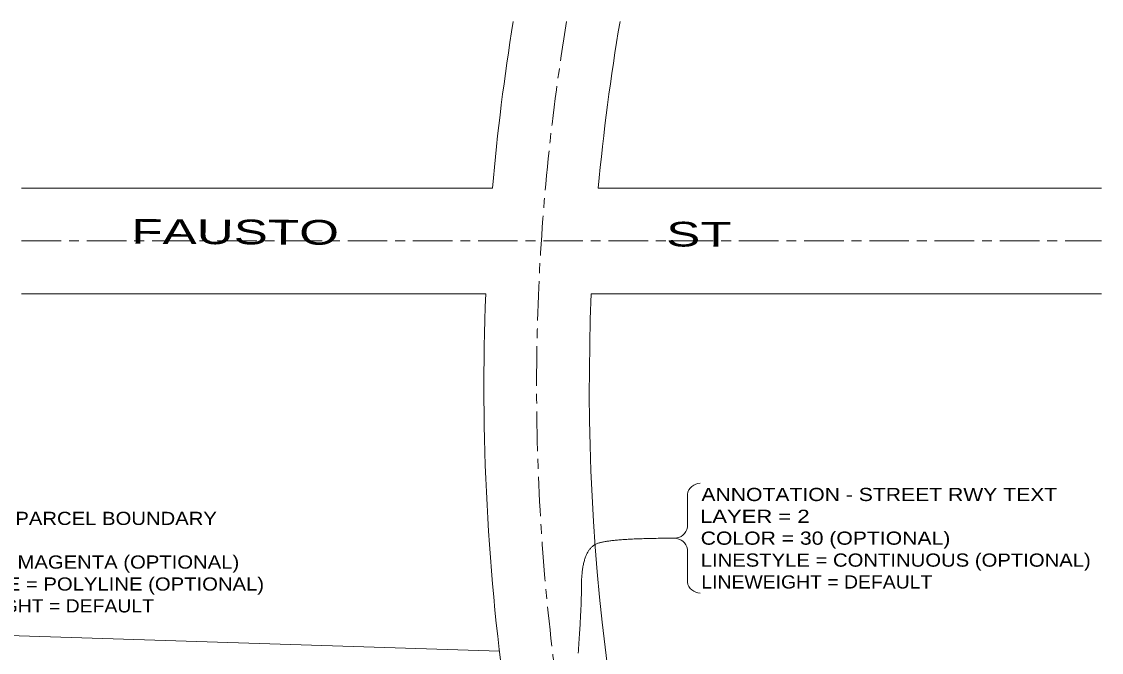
# Model space of a CAD drawing. Extents: x 6387474 to 6390971, y 1972046 to 1973920.
# Drawn here: x 6389237 to 6389892, y 1973538 to 1973920 of the extents above; entities that cross this region are included whole.
import ezdxf

# ---------------------------------------------------------------- set-up
doc = ezdxf.new("R2010")
doc.units = 0
doc.header["$LTSCALE"] = 4
doc.linetypes.add('LONG_DASH_SHORT_DASH', pattern=[9.9, 6, -1.2, 1.5, -1.2])
for name, color, linetype, lineweight in [('1', 7, 'Continuous', 13), ('2', 7, 'LONG_DASH_SHORT_DASH', 13), ('4', 7, 'Continuous', 13), ('8', 7, 'Continuous', 13)]:
    doc.layers.add(name, color=color, linetype=linetype, lineweight=lineweight)

msp = doc.modelspace()

# ---------------------------------------------------------------- linework, layer by layer
at = {"layer": '1'}
msp.add_line((6389526.666, 1973538.455), (6389072.576, 1973552.734), dxfattribs=at)
at = {"layer": '2'}
msp.add_line((6389236.569, 1973787.317), (6389892.252, 1973787.317), dxfattribs=at)
msp.add_arc((6390899.27, 1973699.338), 1350, 170.57423, 198.92361, dxfattribs=at)
at = {"layer": '4'}
for p, q in [((6389236.569, 1973819.317), (6389522.488, 1973819.317)), ((6389586.742, 1973819.317), (6389892.252, 1973819.317)), ((6389236.569, 1973755.317), (6389518.404, 1973755.317)), ((6389582.459, 1973755.317), (6389892.252, 1973755.317))]:
    msp.add_line(p, q, dxfattribs=at)
for radius, start, end in [(1382, 170.7944, 175.01954), (1318, 170.34322, 174.77704), (1382, 177.67854, 198.92361), (1318, 177.56575, 198.92361)]:
    msp.add_arc((6390899.27, 1973699.338), radius, start, end, dxfattribs=at)
at = {"layer": '8'}
for p, q in [((6389640.806, 1973633.558), (6389640.806, 1973613.578)), ((6389640.806, 1973580.272), (6389640.806, 1973600.252))]:
    msp.add_line(p, q, dxfattribs=at)
for points in [[(6389632.92, 1973606.914), (6389631.634, 1973606.914), (6389630.365, 1973606.914), (6389629.112, 1973606.904), (6389627.876, 1973606.904), (6389626.656, 1973606.894), (6389625.452, 1973606.884), (6389624.266, 1973606.864), (6389623.095, 1973606.854), (6389621.942, 1973606.834), (6389620.805, 1973606.814), (6389619.684, 1973606.794), (6389618.58, 1973606.774), (6389617.493, 1973606.754), (6389616.422, 1973606.724), (6389615.368, 1973606.694), (6389614.33, 1973606.664), (6389613.309, 1973606.634), (6389612.304, 1973606.604), (6389611.316, 1973606.564), (6389610.345, 1973606.524), (6389609.39, 1973606.484), (6389608.452, 1973606.444), (6389607.53, 1973606.404), (6389606.625, 1973606.354), (6389605.736, 1973606.304), (6389604.864, 1973606.254), (6389604.008, 1973606.204), (6389603.169, 1973606.154), (6389602.347, 1973606.094), (6389601.541, 1973606.044), (6389600.751, 1973605.984), (6389599.979, 1973605.924), (6389599.222, 1973605.854), (6389598.483, 1973605.794), (6389597.76, 1973605.724), (6389597.053, 1973605.654), (6389596.363, 1973605.584), (6389595.69, 1973605.514), (6389595.033, 1973605.434), (6389594.392, 1973605.364), (6389593.769, 1973605.284), (6389593.161, 1973605.204), (6389592.571, 1973605.124), (6389591.997, 1973605.034), (6389591.439, 1973604.944), (6389590.898, 1973604.864), (6389590.374, 1973604.774), (6389589.866, 1973604.674), (6389589.375, 1973604.584)], [(6389589.375, 1973604.584), (6389588.9, 1973604.484), (6389588.442, 1973604.384), (6389588, 1973604.284), (6389587.575, 1973604.184), (6389587.162, 1973604.074), (6389586.757, 1973603.954), (6389586.36, 1973603.814), (6389585.971, 1973603.654), (6389585.589, 1973603.484), (6389585.216, 1973603.304), (6389584.85, 1973603.104), (6389584.492, 1973602.894), (6389584.142, 1973602.664), (6389583.8, 1973602.414), (6389583.466, 1973602.164), (6389583.14, 1973601.884), (6389582.821, 1973601.604), (6389582.51, 1973601.294), (6389582.208, 1973600.984), (6389581.913, 1973600.644), (6389581.626, 1973600.304), (6389581.347, 1973599.944), (6389581.075, 1973599.564), (6389580.812, 1973599.174), (6389580.556, 1973598.764), (6389580.309, 1973598.344), (6389580.069, 1973597.914), (6389579.837, 1973597.454), (6389579.613, 1973596.994), (6389579.396, 1973596.514), (6389579.188, 1973596.024), (6389578.987, 1973595.514), (6389578.795, 1973594.984), (6389578.61, 1973594.444), (6389578.433, 1973593.894), (6389578.264, 1973593.324), (6389578.103, 1973592.744), (6389577.949, 1973592.144), (6389577.804, 1973591.534), (6389577.666, 1973590.904), (6389577.536, 1973590.264), (6389577.415, 1973589.604), (6389577.3, 1973588.934), (6389577.194, 1973588.244), (6389577.096, 1973587.544), (6389577.006, 1973586.824), (6389576.923, 1973586.094), (6389576.848, 1973585.344), (6389576.781, 1973584.584), (6389576.722, 1973583.814), (6389576.671, 1973583.024)], [(6389576.671, 1973583.024), (6389576.628, 1973582.214), (6389576.593, 1973581.394), (6389576.565, 1973580.564), (6389576.546, 1973579.714), (6389576.534, 1973578.844), (6389576.53, 1973577.964), (6389576.528, 1973577.074), (6389576.522, 1973576.144), (6389576.512, 1973575.204), (6389576.498, 1973574.224), (6389576.481, 1973573.234), (6389576.459, 1973572.214), (6389576.433, 1973571.164), (6389576.404, 1973570.104), (6389576.371, 1973569.004), (6389576.333, 1973567.894), (6389576.292, 1973566.754), (6389576.247, 1973565.584), (6389576.198, 1973564.394), (6389576.144, 1973563.184), (6389576.087, 1973561.944), (6389576.027, 1973560.684), (6389575.962, 1973559.394), (6389575.893, 1973558.084), (6389575.82, 1973556.744), (6389575.743, 1973555.384), (6389575.663, 1973554.004), (6389575.578, 1973552.594), (6389575.49, 1973551.164), (6389575.397, 1973549.704), (6389575.301, 1973548.224), (6389575.201, 1973546.714), (6389575.097, 1973545.194), (6389574.988, 1973543.634), (6389574.876, 1973542.054), (6389574.76, 1973540.454), (6389574.64, 1973538.824), (6389574.517, 1973537.174)]]:
    msp.add_lwpolyline(points, dxfattribs=at)
for centre, start, end in [((6389648.695, 1973632.221), 90, 170.38048), ((6389632.92, 1973614.915), 270, 350.38048), ((6389632.92, 1973598.915), 9.61952, 90), ((6389648.695, 1973581.609), 189.61952, 270)]:
    msp.add_arc(centre, 8, start, end, dxfattribs=at)

# ---------------------------------------------------------------- texts
at = {"layer": '2', "width": 1.55}
msp.add_text('FAUSTO                       ST', height=15, rotation=359.712, dxfattribs=at).set_placement((6389303.144, 1973785.61))
at = {"layer": '8'}
for s, width, p in [('ANNOTATION - STREET RWY TEXT', 1.2, (6389649.34, 1973629.455)), ('TRACT & PARCEL BOUNDARY', 1.15, (6389176.692, 1973614.945)), ('LAYER = 2', 1.25, (6389648.528, 1973616.207)), ('COLOR = 30 (OPTIONAL)', 1.2, (6389648.92, 1973602.949)), ('COLOR = MAGENTA (OPTIONAL)', 1.15, (6389176.272, 1973588.439)), ('LINESTYLE = CONTINUOUS (OPTIONAL)', 1.15, (6389648.92, 1973589.629)), ('LINETYPE = POLYLINE (OPTIONAL)', 1.15, (6389176.272, 1973575.119)), ('LINEWEIGHT = DEFAULT', 1.1, (6389649.312, 1973576.371)), ('LINEWEIGHT = DEFAULT', 1.1, (6389176.664, 1973561.861))]:
    msp.add_text(s, height=8, dxfattribs=dict(at, width=width)).set_placement(p)

doc.saveas('drawing.dxf')
